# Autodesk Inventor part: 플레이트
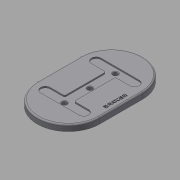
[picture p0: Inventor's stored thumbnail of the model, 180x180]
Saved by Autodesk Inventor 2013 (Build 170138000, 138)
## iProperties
Created: 2016-08
Part Number: 플레이트
Material: 일반
Document SubType Name: Modeling
Designer: mduedu
Density: 1 g/cm^3
Mass: 304.482 g
Surface Area: 591.117 cm^2
Volume: 304.482 cm^3
Author: mduedu
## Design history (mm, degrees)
sketch "스케치1" dims "d0" = 220, "d2" = 130
  geometry: L1 (45, 65)-(-45, 65); L2 (-45, 65)-(-45, -65); L3 (-45, -65)-(45, -65); L4 (45, -65)-(45, 65); L5 (45, 65)-(-45, -65); L6 (-45, 65)-(45, -65); 5 further points
  constraints: 12 end point, 5 midpoint, 2 parallel, 2 vertical alignment, 1 coincident, 1 horizontal, 1 perpendicular, 4 other
extrude "돌출1" new body sketch "스케치1" distance "d3" = 13; taper "d4" = 0 deg
sketch "스케치2"
  geometry: L1 (-63, -50)-(63, -50); L2 (63, -50)-(63, 50); L3 (63, 50)-(-63, 50); L4 (-63, 50)-(-63, -50); L5 (-63, -50)-(63, 50); L6 (63, -50)-(-63, 50); L7 (-63, 50)-(-43, 50); L8 (-43, 50)-(-43, -50); L9 (-43, -50)-(-63, -50); L10 (-63, -50)-(-63, 50); L11 (63, 50)-(43, 50); L12 (43, 50)-(43, -50); L13 (43, -50)-(63, -50); L14 (63, -50)-(63, 50); L15 (-43, -10)-(43, -10); L16 (43, -10)-(43, 10); L17 (43, 10)-(-43, 10); L18 (-43, 10)-(-43, -10); L19 (-43, -10)-(43, 10); L20 (43, -10)-(-43, 10); 1 further point
  constraints: 40 end point, 8 parallel, 4 horizontal, 4 midpoint, 4 perpendicular, 3 point on line
  dimensions: "d18" = 126 distance of L3.end L2.end; "d19" = 100 distance of L2.end L1.end; "d20" = 20 distance of L8.end L9.end; "d21" = 20 distance of L12.end L13.end (= d20); "d22" = 20 distance of L15.end L16.end
extrude "돌출3" cut sketch "스케치2" distance "d23" = 3; taper "d24" = 0 deg
fillet "모깎기2"
fillet "모깎기3"
fillet "모깎기4"
fillet "모깎기5"
fillet "모깎기6" dims "d25" = 3
sketch "스케치4"
  geometry: L1 (-43, -40)-(-43, -13) reference; L2 (-40, -10)-(40, -10) reference; L3 (43, -13)-(43, -40) reference; L4 (63, -40)-(63, 40) reference; L5 (43, 40)-(43, 13) reference; L6 (40, 10)-(-40, 10) reference; L7 (-43, 13)-(-43, 40) reference; L8 (-63, 40)-(-63, -40) reference; L9 (45, -65)-(-45, -65) reference; L10 (-45, 65)-(45, 65) reference; L11 (-53, 40)-(-53, -40); L12 (53, 40)-(53, -40); L13 (-53, 0)-(53, 0); C1 r 5 at (-53, 0); C2 r 5 at (0, 0); C3 r 5 at (53, 0); A1 r 10 centre (-53, -40) between (-63, -40) and (-43, -40) reference; A2 r 3 centre (-40, -13) between (-40, -10) and (-43, -13) reference; A3 r 3 centre (40, -13) between (43, -13) and (40, -10) reference; A4 r 10 centre (53, -40) between (43, -40) and (63, -40) reference; A5 r 10 centre (53, 40) between (63, 40) and (43, 40) reference; A6 r 3 centre (40, 13) between (40, 10) and (43, 13) reference; A7 r 3 centre (-40, 13) between (-43, 13) and (-40, 10) reference; A8 r 10 centre (-53, 40) between (-43, 40) and (-63, 40) reference; A9 r 65 centre (45, 0) between (45, -65) and (45, 65) reference; A10 r 65 centre (-45, 0) between (-45, 65) and (-45, -65) reference; 1 further point
  constraints: 6 end point, 3 centre point, 3 coincident, 2 midpoint, 1 parallel, 1 perpendicular
  dimensions: "d26" = 10 diameter of C1; "d27" = 10 diameter of C2; "d28" = 10 diameter of C3
extrude "돌출4" cut sketch "스케치4" stored distance "d29" = 3; taper "d30" = 0 deg
chamfer "모따기2" distance "d31" = 1; stored, may be unused: second distance "d32" = 2, angle "d33" = 45 deg
fillet "모깎기1" dims "d14" = 3
sketch "스케치3"
  geometry: L1 (-45, -65)-(45, -65) reference; 2 further points
  constraints: 1 vertical alignment, 1 other
  dimensions: "d15" = 12 distance from line of point (0, -53) L1
feature "엠보싱1" sketch "스케치3" dims "d0" = 220, "d2" = 130, "d16" = 0.5, "d17" = 0
node "솔리드1"
node "절단 모서리 투영1"
